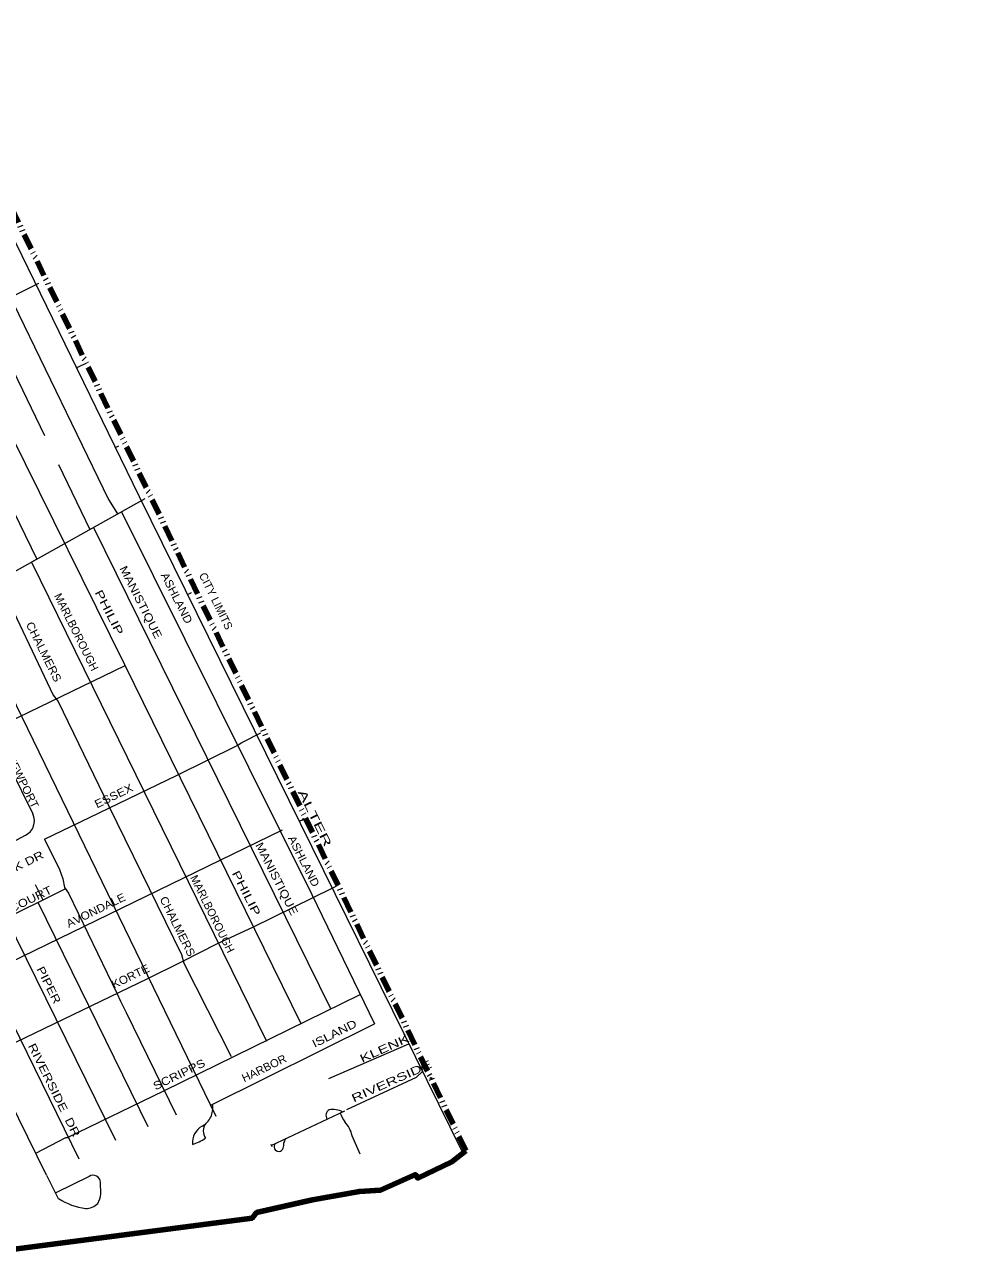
# Model space of a CAD drawing. Extents: x 34705 to 138605, y 34275 to 143551.
# Drawn here: x 127853 to 136773, y 108664 to 120262 of the extents above; entities that cross this region are included whole.
import ezdxf
from ezdxf.enums import TextEntityAlignment as Align

# ---------------------------------------------------------------- set-up
doc = ezdxf.new("R2010")
doc.units = 0
doc.header["$LTSCALE"] = 30
doc.header["$PDMODE"] = 32
doc.header["$PDSIZE"] = 15
doc.linetypes.add('DASH_DOUBLE_DOT', pattern=[9.2, 5, -1.2, 0.3, -1.2, 0.3, -1.2])
for name, color, linetype, lineweight in [('1', 7, 'Continuous', 13), ('11', 7, 'Continuous', 13), ('58', 7, 'Continuous', 106), ('59', 7, 'DASH_DOUBLE_DOT', 106)]:
    doc.layers.add(name, color=color, linetype=linetype, lineweight=lineweight)

msp = doc.modelspace()

# ---------------------------------------------------------------- linework, layer by layer
at = {"layer": '1'}
for p, q in [((127985.18, 117839.54), (127985.99, 117839.94)), ((128336.36, 117046.08), (128368.81, 117061.96)), ((128368.81, 117061.96), (128429, 117091.39)), ((128700.53, 116299.61), (128736.29, 116317.12)), ((129378.13, 114920.76), (129415.46, 114940.52)), ((129415.67, 114940.08), (129416.47, 114940.51)), ((127605.04, 113519.8), (127927.94, 112865.73)), ((130427.65, 112797.28), (130464.2, 112814.83)), ((130464.4, 112814.42), (130465.22, 112814.82)), ((127199.72, 111223.43), (130270.53, 112715.78)), ((127040.82, 111574.83), (128233.04, 112165.29)), ((127951.39, 112205.85), (128021.91, 112060.73)), ((130773.1, 112188.72), (130773.92, 112189.11)), ((127975.71, 112037.85), (129005.82, 109935.5)), ((127679.61, 111891.2), (128703.46, 109807.53)), ((127337.15, 111721.59), (128360.39, 109633.04)), ((129596.04, 110135.82), (131131.03, 110897.71)), ((130704.07, 110387.31), (131454.49, 110710.77)), ((130164.56, 109759.65), (130852.57, 110083.06)), ((130998.72, 109677.53), (130921.66, 109848.66)), ((130159.46, 109771.63), (130168.66, 109749.99)), ((128055.98, 109481.54), (128165.34, 109260.64)), ((128456.09, 109468.49), (128142.88, 109315.4)), ((128566.11, 109305.23), (128563.49, 109412.24)), ((130020.03, 109122.11), (129993.02, 109089.38))]:
    msp.add_line(p, q, dxfattribs=at)
for points in [[(123399.09, 126780.52), (123922.06, 125697.22), (124525.96, 124452.92), (124932.56, 123823.32), (125249.56, 123320.82), (126192.76, 121460.32), (126246.66, 121316.72), (126714.56, 120374.62), (126792.26, 120242.92), (127222.76, 119375.52), (127240.76, 119291.82), (128923.96, 115841.62), (131948.16, 109709.82)], [(122916.79, 126437.65), (122924.96, 126421.12), (122924.96, 126418.12), (124029.72, 124169.33), (123960.31, 124135.25), (124517.06, 122993.32), (124546.96, 122927.52), (124965.46, 122072.02), (125491.66, 121037.12), (125509.66, 120959.32), (125898.26, 120187.62), (125940.16, 120079.92), (127207.86, 117506.12), (127255.66, 117404.42), (127722.06, 116423.32), (128789.46, 114265.32), (130440.68, 110901.16)], [(123155.77, 126527.83), (123636.56, 125553.62), (124246.46, 124327.32), (124306.26, 124249.52), (124563.36, 123762.02), (124588.61, 123710.58), (124480.19, 123657.04), (124503.56, 123618.42), (125064.16, 122483.32), (125094.06, 122411.52), (125398.96, 121825.22), (125410.96, 121795.32), (127452.96, 117619.82), (128038.4, 116411.89)], [(122679.82, 126325.78), (122912.96, 125840.82), (123176.06, 125302.42), (123235.86, 125185.72), (123487.06, 124689.22), (123791.5, 124052.38), (123701.92, 124008.41), (125222.66, 120923.42), (125246.56, 120857.62), (125593.36, 120115.82), (125635.16, 120008.12), (126932.76, 117374.52), (127964.97, 115253.63), (127916.54, 115226.55), (130119.86, 110735.72)], [(121998.48, 126059.55), (123121.38, 123768.69), (123133.01, 123652.36), (124804.73, 120222.06), (124921.02, 120065.01), (127412.16, 114944.42), (127287.96, 114874.95), (129645.43, 110034.38)], [(123460.16, 123835.32), (125301.86, 120082.92), (125361.66, 119945.32), (126683.16, 117247.42), (126707.06, 117139.72), (127706.07, 115108.82), (127606.4, 115053.07), (128119.76, 113978.12), (128167.56, 113918.32), (128639.96, 112937.22), (129321.66, 111549.32), (129345.56, 111465.62), (129788.06, 110592.22)], [(126557.78, 120062.94), (127745.96, 117649.72), (128636.96, 115811.62), (128723.44, 115677.88), (128759.59, 115698.09), (130544.46, 112111.72), (131131.03, 110897.71)], [(123062.26, 115367.56), (125022.98, 116359.84), (126087.91, 116901.21), (127984.98, 117839.96)], [(128169.44, 116141.52), (128464.38, 115532.97), (128495.94, 115550.63), (130717.86, 111040.82)], [(103390.08, 100620.34), (111287.98, 105212.28), (112213.24, 105742.01), (112517.3, 105916.64), (114001.22, 107220.59), (115042.88, 108140.33), (115378.94, 108454.67), (118009.27, 111231.38), (118294.41, 111464.23), (120540.66, 112907.88), (120691.96, 113012.66), (122079.87, 113725.76), (123691.81, 114016.82), (124355.21, 114109.95), (126298.86, 114360.26), (126409.42, 114383.55), (128980.68, 115821.76)], [(119797.02, 109882.81), (122395.56, 111149.88), (124030.79, 111929.92), (124118.08, 111988.13), (127794.42, 113773.78), (128795.34, 114256.94)], [(128038.12, 112627.68), (128291.97, 112750.71), (128641.13, 112919.52), (129281.25, 113228.04), (129845.72, 113507.46), (129886.46, 113536.57), (130064.72, 113624.54)], [(127542.16, 112393.25), (127625.05, 112457.32), (127689.84, 112560.46), (127739.1, 112601.56), (127860.99, 112665.39)], [(128038.12, 112627.68), (128180.14, 112343.55), (128209.21, 112256.3), (128226.66, 112174.87), (128261.54, 112122.52), (128715.09, 111186.06), (128749.98, 111110.44), (128802.31, 111005.74), (129273.3, 110046.01)], [(127506.37, 110602.69), (129007.74, 111324.52), (129327.8, 111481.69), (129659.5, 111650.51), (129997.02, 111807.68), (130741.89, 112174.41), (130772.9, 112189.13)], [(127955.29, 109684.94), (128236.69, 109834.3), (128254.15, 109834.3), (129156.14, 110270.89), (130997.38, 111174.32)], [(127528.89, 110546.24), (128055.13, 109483.26)], [(130872.83, 110096.25), (131524.59, 110398.95), (131582.78, 110451.34), (131571.43, 110570.59)]]:
    msp.add_lwpolyline(points, dxfattribs=at)
for centre, radius, start, end in [((127793.44, 112799.32), 150, 296.76466, 26.27436), ((129422.03, 110109.77), 193.88, 333.87809, 9.32881), ((130742.53, 110038.63), 65.87, 123.50612, 210.17657), ((130735.17, 109859.22), 236.12, 65.50004, 97.05382), ((129422.03, 110109.77), 193.88, 299.07294, 333.74739), ((129643.83, 109893.84), 117.53, 143.81488, 214.64872), ((131196.57, 110210.25), 414.11, 200.8772, 213.83592), ((130659.21, 109794.2), 268.04, 11.72312, 43.80382), ((129608.25, 109780.87), 184.09, 119.98569, 183.98759), ((129284.9, 110215.29), 468.54, 287.34708, 304.03509), ((130234.24, 109747.28), 44.33, 138.97716, 340.39134), ((130088.94, 109783.74), 193.97, 344.65384, 359.41093), ((130393.58, 109761.95), 112.43, 147.40606, 169.85736), ((128493.91, 109410.04), 69.61, 1.80786, 122.92459), ((128522.45, 109820.97), 661.82, 237.86724, 261.4072), ((128323.61, 109329.32), 243.7, 332.04702, 354.32724), ((128411.54, 109356.45), 190.26, 273.62214, 312.0102)]:
    msp.add_arc(centre, radius, start, end, dxfattribs=at)
for p in [(130464.2, 112814.83), (131661.01, 110389.02)]:
    msp.add_point(p, dxfattribs=at)
at = {"layer": '58'}
msp.add_lwpolyline([(131989.06, 109708.72), (131856.2, 109606.1), (131537.71, 109452.94), (131515.49, 109485.92), (131186.49, 109340.29), (130989.66, 109327.71), (130551.35, 109248.98), (130026.49, 109129.94), (129983.33, 109077.63), (127080.95, 108699.07)], dxfattribs=at)
at = {"layer": '59'}
msp.add_lwpolyline([(131989.06, 109708.72), (126856.28, 120352.83), (127983.73, 120601.28), (129321.71, 120998.46), (130612.42, 121494.12), (133722.19, 123216.65), (134563.84, 124776.42), (136438.38, 130047.1), (136736.54, 131235.05), (136773.12, 131974.15), (125584.57, 138103.26), (128512.62, 143301.1), (34921.35, 140631.52)], dxfattribs=at)

# ---------------------------------------------------------------- texts
at = {"layer": '1'}
msp.add_text('CITY LIMITS', height=75, rotation=296.106, dxfattribs=at).set_placement((129611.36, 114844.57), align=Align.CENTER)
for s, rotation, width, p in [('ALTER', 296.228, 1.8, (130538.89, 112810.59)), ('KLENK        ', 24.119, 1.5, (131392.52, 110701.85)), ('RIVERSIDE   ', 24.196, 1.5, (131364.06, 110352.79))]:
    msp.add_text(s, height=75, rotation=rotation, dxfattribs=dict(at, width=width)).set_placement(p, align=Align.CENTER)
at = {"layer": '11'}
for s, rotation, width, p in [('MANISTIQUE', 296.902, 1.2, (128908.32, 114833.21)), ('ASHLAND', 296.904, 1.1, (129244.4, 114871.7)), ('PHILIP', 296.9, 1.45, (128611.13, 114737.54)), ('CHALMERS', 296.399, 1.1, (127997.62, 114368.53)), ('NEWPORT', 296.398, 1.05, (127801.39, 113151.49)), ('ESSEX', 25.892, 1.15, (128703.25, 113001.03)), ('ASHLAND', 296.904, 1.1, (130435.85, 112406.11)), ('VICTORIA PARK DR', 26.398, 1.25, (127508.21, 112193.8)), ('MANISTIQUE', 296.902, 1.2, (130182.74, 112241.04)), ('PHILIP', 296.9, 1.45, (129896.6, 112106.01)), ('AVERHILL COURT', 25.892, 1.2, (127647.31, 111899.33)), ('AVONDALE', 25.891, 1.1, (128535.56, 111928.7)), ('CHALMERS', 296.399, 1.1, (129251.65, 111795.61)), ('PIPER', 296.397, 1.25, (128045.02, 111245.23)), ('KORTE', 25.889, 1.1, (128860.28, 111309.61)), ('ISLAND', 26.567, 1.25, (130772.02, 110773.89)), ('RIVERSIDE  DR', 296.398, 1.3, (128095.27, 110261.12)), ('SCRIPPS', 25.998, 1.2, (129316.06, 110390.26)), ('HARBOR', 26, 1.05, (130112.54, 110449.08))]:
    msp.add_text(s, height=75, rotation=rotation, dxfattribs=dict(at, width=width)).set_placement(p, align=Align.CENTER)
for p in [(128302.5, 114553.99), (129578.35, 111912.26)]:
    msp.add_text('MARLBOROUGH', height=75, rotation=296.399, dxfattribs=at).set_placement(p, align=Align.CENTER)

doc.saveas('drawing.dxf')
